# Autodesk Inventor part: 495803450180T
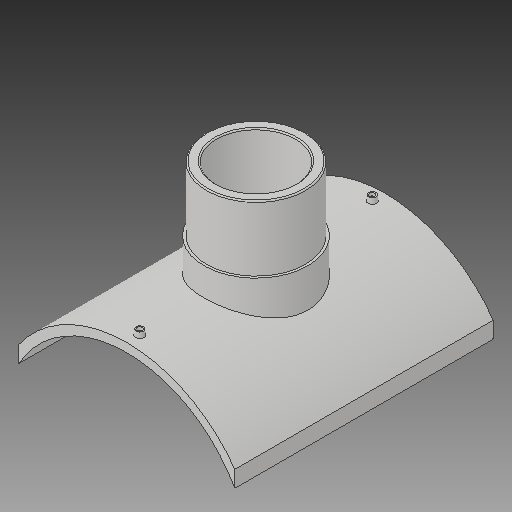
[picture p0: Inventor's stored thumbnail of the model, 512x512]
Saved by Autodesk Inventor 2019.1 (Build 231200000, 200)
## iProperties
Created: 2017-10
Part Number: 495803450180T
Material: Generic
Description: PLASSON BRANCH SADDLE  450x180
Document SubType Name: Modeling
Designer: KIM
Mass: 2754.05 g
Surface Area: 3037.44 cm^2
Volume: 2754.05 cm^3
Density: 1 g/cm^3
Appearance: Default
Author: KIM
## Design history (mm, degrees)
derived "495803.ipt"
feature "Solid1::495803.ipt"
tag "TaggingFeature1"
body "Solid1"
other parameters: "d1" = 16, "d2" = 393, "d4" = 0, "d12" = 250.6, "d13" = 14, "d14" = 211.5, "d16" = 5 deg, "d18" = 4, "d19" = 14, "d20" = 0, "d21" = 3, "d22" = 0, "d24" = 189, "d25" = 16, "d26" = 144, "d28" = 0, "d29" = 9.6, "d31" = 0, "d32" = 84.5, "d33" = 0, "d34" = 4.5, "d37" = 118.3, "d38" = 0, "d39" = 2.25, "B_" = 393, "H_" = 169, "x_" = 16, "D_" = 16
